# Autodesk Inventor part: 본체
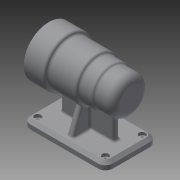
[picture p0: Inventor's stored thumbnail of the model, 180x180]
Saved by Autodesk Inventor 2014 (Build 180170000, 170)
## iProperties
Created: 2016-06
Part Number: 본체
Material: 일반
Document SubType Name: Modeling
Designer: SEC
Density: 1 g/cm^3
Appearance: 기본값
Author: SEC
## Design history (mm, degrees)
sketch "스케치1"
  geometry: L1 (-56, 35)-(56, 35); L2 (56, 35)-(56, -35); L3 (56, -35)-(-56, -35); L4 (-56, -35)-(-56, 35); 3 further points
  constraints: 8 end point, 2 midpoint, 2 parallel, 1 horizontal, 1 horizontal alignment, 1 perpendicular, 1 vertical alignment
  dimensions: "d0" = 70 distance between parallel lines of L3 L1; "d1" = 112 distance between parallel lines of L4 L2
extrude "돌출1" new body sketch "스케치1" distance "d2" = 10; taper "d3" = 0 deg
sketch "스케치3"
  geometry: L1 (-56, 35)-(-56, -35) reference; L2 (56, -35)-(56, 35) reference; L3 (-36, 4)-(36, 4); L4 (36, 4)-(36, -4); L5 (36, -4)-(-36, -4); L6 (-36, -4)-(-36, 4); 2 further points
  constraints: 8 end point, 2 parallel, 1 horizontal, 1 horizontal alignment, 1 midpoint, 1 perpendicular
  dimensions: "d4" = 8 distance between parallel lines of L5 L3; "d5" = 20 distance between parallel lines of L4 L2; "d6" = 20 distance between parallel lines of L1 L6
extrude "돌출2" join sketch "스케치3" distance "d7" = 70; taper "d8" = 0 deg
sketch "스케치4"
  geometry: L1 (35, 10)-(-35, 10) reference; L2 (4, 10)-(4, 80) reference; L3 (28, 10)-(4, 75.939); 1 further point
  constraints: 2 end point, 2 point on line
  dimensions: "d9" = 7 distance of L3.start L1.start; "d10" = 110 deg angle of L3 L1
feature "리브1" sketch "스케치4" dims "d11" = 1, "d12" = 8, "d13" = 0, "d14" = 0, "d15" = 1, "d16" = 1
node "작업 평면1"
sketch "스케치5"
  geometry: L1 (0, 70)-(0, 0) reference; C1 r 25 at (-70, 35); 2 further points
  constraints: 1 centre point, 1 horizontal alignment, 1 midpoint
  dimensions: "d17" = 70 distance of C1.centre point (0, 35); "d18" = 50 diameter of C1
extrude "돌출3" join sketch "스케치5" distance "d19" = 25; taper "d20" = 0 deg
sketch "스케치11"
  geometry: C1 r 27 at (70, 35); A1 r 25 centre (70, 35) between (45.322, 31) and (45.322, 39) reference; 1 further point
  constraints: 1 centre point, 1 coincident
  dimensions: "d34" = 54 diameter of C1
extrude "돌출8" join sketch "스케치11" distance "d35" = 20; taper "d36" = 0 deg
sketch "스케치12"
  geometry: C1 r 30 at (70, 35); A1 r 27 centre (70, 35) between (43.298, 31) and (43.298, 39) reference; 1 further point
  constraints: 1 centre point, 1 coincident
  dimensions: "d37" = 60 diameter of C1
extrude "돌출9" join sketch "스케치12" distance "d38" = 39; taper "d39" = 0 deg
sketch "스케치13"
  geometry: C1 r 34 at (70, 35); A1 r 30 centre (70, 35) between (40.268, 31) and (40.268, 39) reference; 1 further point
  constraints: 1 centre point, 1 coincident
  dimensions: "d40" = 68 diameter of C1
extrude "돌출10" join sketch "스케치13" distance "d41" = 28; taper "d42" = 0 deg
sketch "스케치14"
  geometry: 5 further points
  constraints: 1 horizontal alignment, 1 vertical alignment
  dimensions: "d43" = 46 horizontal distance of point (-46, -25) point (0, 0); "d44" = 25 vertical distance of point (-46, -25) point (0, 0); "d45" = 50 distance of point (-46, 25) point (-46, -25); "d46" = 92 distance of point (46, -25) point (-46, -25); "d47" = 50 distance of point (46, 25) point (46, -25); "d48" = 92 distance of point (-46, 25) point (46, 25)
hole "구멍1" sketch "스케치14" at (46, -25), (-46, -25), (-46, 25), (46, 25) diameter "d49" = 5; stored, may be unused: countersink angle "d53" = 90 deg, drill point angle "d55" = 118 deg; dims "d50" = 6, "d51" = 9, "d52" = 4, "d54" = 8
fillet "모깎기1" dims "d56" = 10
chamfer "모따기1" distance "d57" = 4; stored, may be unused: second distance "d58" = 2, angle "d59" = 45 deg
sketch "스케치15"
  geometry: C1 r 34 at (0, 0) reference; C2 r 21 at (0, 0); 1 further point
  constraints: 1 centre point, 1 coincident
  dimensions: "d60" = 42 diameter of C2
extrude "돌출11" cut sketch "스케치15" distance "d61" = 15; taper "d62" = 0 deg
sketch "스케치16"
  geometry: C1 r 21 at (0, 0) reference; C2 r 24 at (0, 0); 1 further point
  constraints: 1 centre point, 1 coincident
  dimensions: "d63" = 48 diameter of C2
extrude "돌출12" cut sketch "스케치16" distance "d64" = 54; taper "d65" = 0 deg
sketch "스케치17"
  geometry: C1 r 24 at (0, 0) reference; C2 r 21 at (0, 0); 1 further point
  constraints: 1 centre point, 1 coincident
  dimensions: "d66" = 42 diameter of C2
extrude "돌출13" cut sketch "스케치17" distance "d67" = 12; taper "d68" = 0 deg
sketch "스케치18"
  geometry: C1 r 21 at (0, 0) reference; C2 r 17.5 at (0, 0); 1 further point
  constraints: 1 centre point, 1 coincident
  dimensions: "d69" = 35 diameter of C2
extrude "돌출14" cut sketch "스케치18" distance "d70" = 18; taper "d71" = 0 deg
sketch "스케치19"
  geometry: C1 r 17.5 at (0, 0) reference; C2 r 16 at (0, 0); 1 further point
  constraints: 1 centre point, 1 coincident
  dimensions: "d72" = 32 diameter of C2
extrude "돌출15" cut sketch "스케치19" distance "d73" = 4; taper "d74" = 0 deg
sketch "스케치20"
  geometry: C1 r 16 at (0, 0) reference; C2 r 10.5 at (0, 0); 1 further point
  constraints: 1 centre point, 1 coincident
  dimensions: "d75" = 21 diameter of C2
extrude "돌출16" cut sketch "스케치20" distance "d76" = 3; taper "d77" = 0 deg
fillet "모깎기2" dims "d78" = 10
fillet "모깎기3" dims "d79" = 3
fillet "모깎기4" dims "d80" = 0.3
fillet "모깎기5" dims "d81" = 3
chamfer "모따기2" distance "d82" = 1; stored, may be unused: second distance "d83" = 2, angle "d84" = 45 deg
sketch "스케치21"
  geometry: C1 r 34 at (0, 0) reference; 2 further points
  constraints: 1 vertical alignment
  dimensions: "d85" = 26 distance of C1.centre point (0, 26)
hole "구멍2" sketch "스케치21" at (0, 26) diameter "d86" = 3.242; stored, may be unused: countersink angle "d90" = 90 deg, drill point angle "d92" = 118 deg; dims "d87" = 8, "d88" = 9, "d89" = 4, "d91" = 11
fillet "모깎기6" dims "d96" = 3
fillet "모깎기7" dims "d97" = 3
fillet "모깎기8" dims "d98" = 3
fillet "모깎기9" dims "d99" = 3
fillet "모깎기10" dims "d100" = 3
node "작업 평면2"
sketch "스케치22"
  geometry: L1 (56, 36)-(56, 104) reference; 2 further points
  constraints: 1 other
  dimensions: "d102" = 48 distance from line of point (8, 70) L1; "d103" = 70 vertical distance of point (8, 70) point (0, 0)
feature "엠보싱1" sketch "스케치22" dims "d104" = 0.5, "d105" = 0
node "솔리드1"
mirror "대칭1"
pattern_circular "원형 패턴1" dims angle "d94" = 360 deg
other parameters: "d101" = 43.25
